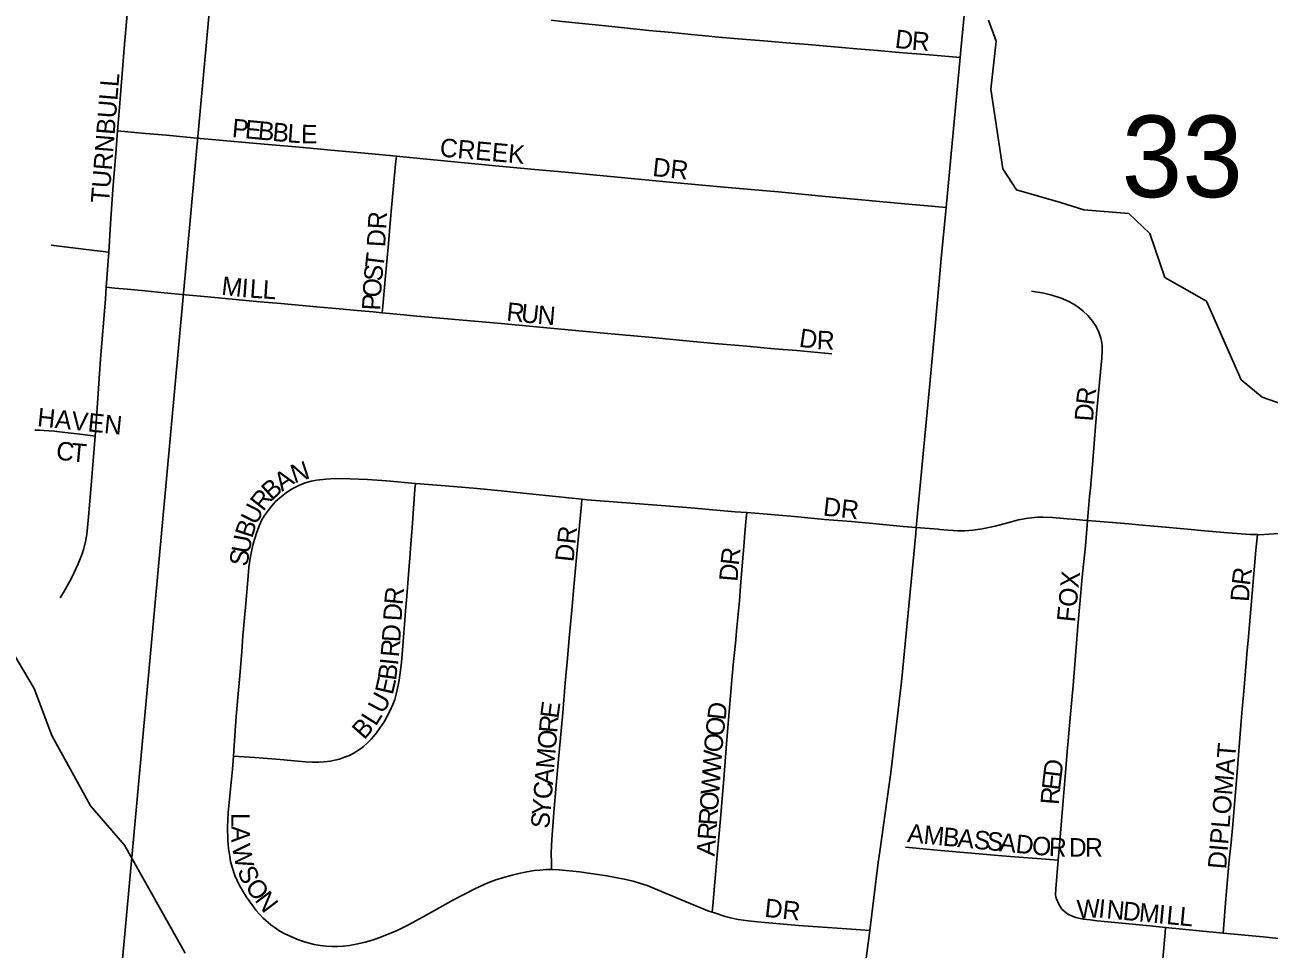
# Model space of a CAD drawing. Extents: x 1410790 to 1770854, y 448063 to 770588.
# Drawn here: x 1528142 to 1531514, y 635499 to 638002 of the extents above; entities that cross this region are included whole.
import ezdxf

# ---------------------------------------------------------------- set-up
doc = ezdxf.new("R2010")
doc.units = 0
for name, color, linetype in [('GM_X_City_Street', 7, 'Continuous'), ('GM_X_City_Street_Text', 7, 'Continuous'), ('GM_X_Minor_River', 7, 'Continuous'), ('GM_X_Section', 7, 'Continuous'), ('GM_X_Section_Text', 7, 'Continuous')]:
    doc.layers.add(name, color=color, linetype=linetype)

msp = doc.modelspace()

# ---------------------------------------------------------------- linework, layer by layer
at = {"layer": 'GM_X_City_Street'}
for points in [[(1528393.4, 637715.4), (1528397.6, 637767.9), (1528412.4, 637949.9), (1528431.1, 638161.5), (1528439.8, 638248), (1528453.8, 638381.2), (1528472.3, 638566.1), (1528485.8, 638700.3), (1528490.8, 638753.3), (1528497.4, 638828.5)], [(1530677.1, 637913.9), (1530679.1, 637934.6), (1530693.2, 638084.8), (1530711.3, 638277.1)], [(1529568.2, 638014.9), (1529597.9, 638011.6), (1529652.5, 638005.9), (1529706.4, 638000.4), (1529767.2, 637994.1), (1529833.5, 637987.6), (1529896.2, 637981.5), (1529947.7, 637976.4), (1529987.2, 637972.5), (1530022.2, 637969.1), (1530075.5, 637964.6), (1530155.9, 637957.9), (1530206.6, 637953.7), (1530265.1, 637948.9), (1530346.6, 637941.8), (1530386.4, 637938.4), (1530453.1, 637932.7), (1530521.5, 637926.8), (1530583.4, 637921.9), (1530625.5, 637918.3), (1530677.1, 637913.9)], [(1530638.8, 637508.1), (1530677.1, 637913.9)], [(1528369.5, 637386.9), (1528374.5, 637463.3), (1528380.6, 637556.3), (1528389.5, 637665.8), (1528393.4, 637715.4)], [(1528393.4, 637715.4), (1528420.9, 637712.9), (1528469.4, 637708.6), (1528525.8, 637703.5), (1528617.1, 637694.8), (1528659.4, 637691.2), (1528770.2, 637681.5), (1528886.8, 637671.3), (1528972.7, 637663.3), (1529072.3, 637654), (1529148.9, 637646.8)], [(1529110.4, 637222.5), (1529112.1, 637241), (1529118.6, 637312.6), (1529127.4, 637410.2), (1529133.4, 637476.5), (1529136.1, 637506.6), (1529141.6, 637566.5), (1529146.9, 637625.2), (1529148.9, 637646.8)], [(1529148.9, 637646.8), (1529212.2, 637640.9), (1529316, 637630.6), (1529399, 637622.7), (1529514.7, 637611.6), (1529596.3, 637604.1), (1529739.6, 637590.5), (1529804.3, 637584.7), (1529908.9, 637575), (1530037.8, 637563.2), (1530151.9, 637552.9), (1530184.4, 637549.8), (1530301.8, 637538.2), (1530399.7, 637529.2), (1530468.2, 637523.4), (1530536.6, 637516.7), (1530609.3, 637510.6), (1530638.8, 637508.1)], [(1530558, 636640.9), (1530594.7, 637029.9), (1530608, 637176.9), (1530620.3, 637307.5), (1530625.8, 637369.6), (1530638.8, 637508.1)], [(1528213.4, 637406.2), (1528249.8, 637401.7), (1528330.9, 637391.7), (1528369.5, 637386.9)], [(1528362.7, 637291.6), (1528369.5, 637386.9)], [(1528332.9, 636888.4), (1528337.5, 636951.2), (1528347.2, 637097.6), (1528353.2, 637172.6), (1528360.6, 637260.8), (1528362.7, 637291.6)], [(1528362.7, 637291.6), (1528386.2, 637289.4), (1528419.2, 637286.3), (1528467.8, 637281.7), (1528519.8, 637276.8), (1528577.2, 637271.5), (1528638.4, 637265.7), (1528693.7, 637260.5), (1528780.2, 637252.7), (1528835.9, 637247.6), (1528932.6, 637238.8), (1528994.4, 637233.1), (1529042.3, 637228.8), (1529085.7, 637224.8), (1529110.4, 637222.5)], [(1531022.4, 636660.2), (1531027.9, 636725.3), (1531030.4, 636747.9), (1531035.5, 636810.8), (1531040.2, 636868.9), (1531046.6, 636948.7), (1531053.1, 637014.8), (1531060.9, 637100.9), (1531061.9, 637119.4), (1531061.4, 637132.4), (1531060.5, 637141.1), (1531057.9, 637154.1), (1531052.6, 637170.3), (1531045.2, 637185.7), (1531035.8, 637199.8), (1531023, 637215.4), (1531010.7, 637227.1), (1530995.7, 637239.2), (1530983.2, 637247.1), (1530969.8, 637254.5), (1530950.8, 637262.3), (1530925.8, 637270.2), (1530903.6, 637275.8), (1530870.3, 637281.3)], [(1529110.4, 637222.5), (1529169, 637217), (1529194.6, 637214.6), (1529432.6, 637193.9), (1529566.3, 637181.3), (1529711.3, 637167.5), (1529843.3, 637155.3), (1529934.8, 637146.8), (1530011.1, 637139.8), (1530098.9, 637131.8), (1530173.2, 637125.3), (1530234.1, 637120.1), (1530291.1, 637114.9), (1530328.8, 637111.5)], [(1528169, 636904.6), (1528181.4, 636904.5), (1528194.5, 636904), (1528207.7, 636903.2), (1528221.9, 636901.7), (1528236.3, 636900.2), (1528268, 636896.4), (1528298.9, 636892.6), (1528332.9, 636888.4)], [(1528238, 636451.1), (1528247.2, 636465), (1528268.1, 636503.6), (1528286.6, 636542.9), (1528297, 636569.5), (1528302.2, 636584.3), (1528306.6, 636602.8), (1528310.3, 636622), (1528314.8, 636670.2), (1528321.5, 636754.5), (1528332.9, 636888.4)], [(1528707.2, 636022.1), (1528709.2, 636050.2), (1528712.1, 636090.4), (1528714.9, 636129.1), (1528719.5, 636181), (1528724.8, 636239.6), (1528730.3, 636305.1), (1528733, 636347.5), (1528741, 636435.4), (1528745.3, 636487.6), (1528749.2, 636532.4), (1528752.8, 636557.7), (1528757.1, 636580.7), (1528761.2, 636596.6), (1528765.4, 636611.8), (1528770.6, 636628.5), (1528777.7, 636647.2), (1528784.7, 636661.7), (1528791.8, 636673.9), (1528807.7, 636695.6), (1528820.9, 636710.7), (1528833.1, 636721.9), (1528851.6, 636736.1), (1528866.7, 636745.8), (1528877.7, 636751.7), (1528886.2, 636755.8), (1528902, 636761.8), (1528918.4, 636766.8), (1528932.9, 636769.6), (1528957.7, 636772.2), (1528984.3, 636773.6), (1529022.5, 636773.4), (1529070.4, 636771), (1529122, 636767.9), (1529200.4, 636760.7)], [(1528707.2, 636022.1), (1528765.1, 636018.3), (1528834, 636012.4), (1528901.6, 636006.5), (1528922.1, 636005.4), (1528938, 636005.7), (1528953.5, 636006.5), (1528970.1, 636008.5), (1528981.8, 636010.6), (1528995, 636013.9), (1529008.8, 636018.7), (1529021.9, 636024.1), (1529032, 636029.4), (1529041.9, 636035.5), (1529051.4, 636041.9), (1529059.8, 636048.4), (1529070.1, 636057.2), (1529080.7, 636068.1), (1529087.2, 636075.5), (1529094.8, 636084.9), (1529105.2, 636099.3), (1529116.1, 636115.2), (1529124.4, 636129.8), (1529131.2, 636143.9), (1529139.4, 636162.2), (1529144.4, 636175.7), (1529148.6, 636189.7), (1529153.3, 636209.9), (1529156.8, 636227.5), (1529162.7, 636275.6), (1529165.9, 636309.1), (1529169.4, 636355.6), (1529171.6, 636389.8), (1529173.8, 636415.9), (1529177.3, 636454.9), (1529181.6, 636513.7), (1529185.2, 636559.2), (1529188.1, 636596.4), (1529191.6, 636640.4), (1529195.7, 636692.7), (1529199.3, 636744.7), (1529200.4, 636760.7)], [(1529200.4, 636760.7), (1529213.4, 636759.6), (1529314.3, 636751.3), (1529368.2, 636746.9), (1529433, 636740.7), (1529509.6, 636732.5), (1529581.2, 636724.9), (1529651.7, 636717.8)], [(1529569.6, 635715.1), (1529569.3, 635730), (1529568.8, 635761.4), (1529570.1, 635796.5), (1529576.1, 635868.9), (1529582.4, 635943), (1529588.4, 636013.9), (1529592.7, 636061.4), (1529599.7, 636139.6), (1529606.8, 636220.2), (1529612.8, 636286.8), (1529617.7, 636341.1), (1529624.6, 636417.7), (1529631.2, 636490.8), (1529639.2, 636579.6), (1529650.4, 636703.5), (1529651.7, 636717.8)], [(1529651.7, 636717.8), (1529665.9, 636716.3), (1529878.3, 636700.1), (1529947, 636694.4), (1530007, 636689.2), (1530067.6, 636683.9), (1530098.5, 636681.5)], [(1530004.9, 635599.1), (1530006.6, 635617.5), (1530012.3, 635680.9), (1530019.7, 635763.8), (1530026.4, 635842.3), (1530036.2, 635960.4), (1530044.1, 636055), (1530056.2, 636208), (1530062.1, 636269.4), (1530067.8, 636328.2), (1530071.9, 636370.2), (1530078.8, 636442.7), (1530082, 636482.6), (1530087.2, 636548.1), (1530090.7, 636589.9), (1530093.8, 636625.6), (1530097.3, 636666.5), (1530098.5, 636681.5)], [(1530098.5, 636681.5), (1530142.7, 636678.1), (1530227.6, 636670.8), (1530309.5, 636663.2), (1530382.2, 636657.2), (1530439.9, 636652), (1530522.1, 636644.3), (1530558, 636640.9)], [(1530558, 636640.9), (1530617, 636636.6), (1530622.1, 636636.1), (1530644.1, 636633.8), (1530658.3, 636632.8), (1530670.8, 636632.3), (1530690, 636632.3), (1530710.9, 636634.3), (1530736.4, 636637.9), (1530771.4, 636645), (1530812.5, 636656), (1530834.9, 636661.6), (1530861, 636666.3), (1530887.5, 636668.9), (1530900.7, 636669.3), (1530927.2, 636668.2), (1530966.6, 636665), (1530991.6, 636662.6), (1531018.7, 636660.5), (1531022.4, 636660.2)], [(1530942.5, 635740.4), (1530947.8, 635802.9), (1530955.9, 635902.2), (1530962.4, 635977.6), (1530967, 636034.5), (1530969.3, 636063.4), (1530975, 636125.3), (1530982.8, 636213.4), (1530996, 636373.5), (1531004.3, 636464.8), (1531007.1, 636497.3), (1531009.8, 636523.4), (1531016.2, 636591.8), (1531021.3, 636647.2), (1531022.4, 636660.2)], [(1531022.4, 636660.2), (1531090.2, 636654.4), (1531133.5, 636651.1), (1531161.2, 636648.6), (1531201.4, 636644.9), (1531223.3, 636642.9), (1531302.8, 636635.7), (1531329.2, 636633.3), (1531402.4, 636627), (1531438.4, 636624.2), (1531463.9, 636622.2), (1531482.4, 636621.9)], [(1531482.4, 636621.9), (1531488.9, 636621.7), (1531513.9, 636622.7), (1531543.3, 636624.6), (1531575.5, 636627.5), (1531613.3, 636630.7), (1531638.9, 636632.9), (1531685.2, 636636.7), (1531744.3, 636642.4), (1531816.4, 636649.3), (1531864.8, 636653.7), (1531913.6, 636657.8), (1531946.2, 636660.6)], [(1530494.5, 636024), (1530518.1, 636223.4), (1530556.5, 636624.9), (1530558, 636640.9)], [(1531389.7, 635542.5), (1531391.5, 635566.1), (1531396.1, 635624.6), (1531400.8, 635676.7), (1531405.7, 635740.5), (1531411.2, 635787.6), (1531414.8, 635826.7), (1531426.5, 635966.7), (1531438.9, 636116.8), (1531441.6, 636149.4), (1531446.4, 636208.1), (1531455.2, 636309.2), (1531457.3, 636335.3), (1531468.2, 636462.6), (1531478.7, 636579.9), (1531482.4, 636621.9)], [(1528707.2, 636022.1), (1528704.8, 635986.6), (1528693.2, 635869.1), (1528691.3, 635829.5), (1528692.4, 635793.1), (1528694.2, 635771.8), (1528697.2, 635750.3), (1528699.7, 635736.8), (1528703.7, 635721), (1528711.4, 635698.8), (1528717.4, 635685.1), (1528724.2, 635671.6), (1528743.1, 635640.4), (1528757, 635620.3), (1528768.1, 635605.2), (1528788.1, 635582.7), (1528808.3, 635565), (1528833.3, 635548.1), (1528846.3, 635540.8), (1528863.1, 635533.1), (1528883.9, 635524.5), (1528900.3, 635518.8), (1528926, 635511.9), (1528942.8, 635508.7), (1528959, 635507), (1528974.9, 635506.4), (1528989, 635506.2), (1529004.9, 635507.1), (1529022.1, 635509.2), (1529044.2, 635513.3), (1529064.3, 635518), (1529087.1, 635524.8), (1529108.4, 635532.3), (1529151.1, 635550.1), (1529183.6, 635566.4), (1529229.7, 635591.6), (1529304.1, 635632.8), (1529361.6, 635662.9), (1529397, 635678.6), (1529418.8, 635686.7), (1529436.8, 635692.6), (1529463, 635699.8), (1529481, 635704.1), (1529498.3, 635707.7), (1529522.4, 635711.8), (1529538.2, 635713.5), (1529554.6, 635714.7), (1529569.6, 635715.1)], [(1530431.9, 635549.8), (1530443.2, 635638.3), (1530454.8, 635733.6), (1530459.1, 635763.9), (1530489, 635977.3), (1530494.5, 636024)], [(1530528.9, 635775), (1530614.5, 635767.1), (1530789.9, 635752.3), (1530931.9, 635741.2), (1530942.5, 635740.4)], [(1530952.2, 635607.5), (1530945.8, 635617.7), (1530941.3, 635627.1), (1530937.9, 635635.7), (1530936.3, 635640.8), (1530935.6, 635646.4), (1530936, 635662.6), (1530942.5, 635740.4)], [(1529569.6, 635715.1), (1529590.2, 635714.4), (1529645.3, 635709), (1529719.6, 635698), (1529770.7, 635687.9), (1529790.4, 635683.4), (1529808.3, 635678.1), (1529828.3, 635671.6), (1529857.1, 635660.2), (1529923.2, 635631.7), (1529993, 635603), (1530004.9, 635599.1)], [(1530952.2, 635607.5), (1530964.3, 635597.4), (1530970.3, 635592.7), (1530978.6, 635589), (1530990.6, 635585), (1531010.5, 635580.7), (1531029, 635578.4), (1531047.9, 635576.2), (1531181.6, 635563.2), (1531233.4, 635558)], [(1530004.9, 635599.1), (1530011, 635597.1), (1530039.9, 635587.8), (1530058, 635583.3), (1530075.5, 635579.8), (1530102.2, 635575.5), (1530127.8, 635572.8), (1530239.1, 635563.3), (1530369.8, 635554.1), (1530431.9, 635549.8)], [(1530389.2, 635137), (1530390.8, 635183.7), (1530398, 635272.8), (1530416.1, 635426.5), (1530431.9, 635549.8)], [(1531185, 635057.2), (1531187.3, 635079.5), (1531205.2, 635259.2), (1531220.6, 635412.8), (1531232.1, 635543.7), (1531233.4, 635558)], [(1531233.4, 635558), (1531380.6, 635543.3), (1531389.7, 635542.5)], [(1531389.7, 635542.5), (1531498.2, 635532.8), (1531573.3, 635524.6), (1531609.2, 635518.8), (1531638.3, 635511.7), (1531669.8, 635501), (1531697.2, 635489.4), (1531723.9, 635477.5), (1531751.4, 635468.3), (1531779.6, 635461.4), (1531811.6, 635456.3), (1531846.1, 635452.7)]]:
    msp.add_lwpolyline(points, dxfattribs=at)
at = {"layer": 'GM_X_Minor_River'}
for points in [[(1528576.5, 635488.3), (1528411.8, 635780.8), (1528319.7, 635887.1), (1528215.2, 636077.9), (1528167.5, 636205.3), (1528062.7, 636380.1), (1527911, 636722.3), (1527903, 636830.8), (1527937.2, 636942.3), (1527939.9, 637086.7), (1527902.8, 637450.4), (1527991.7, 637699.1), (1527919, 637879.2), (1527866.9, 637982.6), (1527856.3, 638161.3)], [(1530753.8, 638014.8), (1530774.7, 637958.2), (1530760.2, 637828.2), (1530792.2, 637612.9), (1530829.2, 637556), (1530948.7, 637521.3), (1531012.4, 637501.8), (1531134.4, 637491.1), (1531191.4, 637437.7), (1531231.2, 637318.5), (1531344.2, 637253.9), (1531438.3, 637041.2), (1531495.5, 636993.9), (1531678.5, 636929.7)]]:
    msp.add_lwpolyline(points, dxfattribs=at)
at = {"layer": 'GM_X_Section'}
for points in [[(1528881.3, 640647.9), (1528392.9, 635323.7), (1523175.4, 635852.3), (1523663.4, 641153)], [(1534160.3, 640098.2), (1533718.1, 634783.3), (1528392.9, 635323.7), (1528881.3, 640647.9)]]:
    msp.add_lwpolyline(points, close=True, dxfattribs=at)

# ---------------------------------------------------------------- texts
at = {"layer": 'GM_X_City_Street_Text'}
for s, rotation, p in [('D', 353.1203, (1530498.4, 637940.7)), ('R', 355.6207, (1530544.4, 637935.2)), ('TURNBULL', 85.4243, (1528370.5, 637518.4)), ('P', 354.583, (1528702, 637698.9)), ('E', 354.6039, (1528737, 637695.6)), ('B', 354.5769, (1528772.1, 637692.3)), ('B', 354.6007, (1528811.5, 637688.5)), ('L', 355.6693, (1528852, 637684.7)), ('E', 359.1677, (1528890.3, 637681.9)), ('CREEK', 354.9006, (1529265.1, 637646.1)), ('DR', 353.9832, (1529841.6, 637593.3)), ('DR', 86.8222, (1529118.5, 637399.7)), ('T', 82.9461, (1529113.4, 637341.2)), ('S', 84.0746, (1529109.8, 637306.4)), ('M', 353.3742, (1528673.2, 637271.8)), ('I', 355.9304, (1528728, 637265.5)), ('L', 356.1821, (1528750.2, 637263.9)), ('L', 356.2072, (1528785.3, 637261.6)), ('O', 86.5232, (1529107.2, 637263.1)), ('P', 86.9111, (1529105.3, 637228)), ('R', 353.9656, (1529445.7, 637201.7)), ('U', 353.9567, (1529485.1, 637197.5)), ('N', 355.2861, (1529530.1, 637192.8)), ('D', 351.7308, (1530238.5, 637131.2)), ('R', 357.4807, (1530287.4, 637124.4)), ('R', 82.3508, (1531040, 636970.5)), ('HAVEN', 354.1748, (1528174.1, 636915.7)), ('D', 85.7882, (1531036.8, 636927.4)), ('C', 352.5241, (1528224.6, 636826)), ('T', 354.7893, (1528266, 636820.6)), ('N', 18.1343, (1528872.2, 636760.4)), ('A', 33.8174, (1528838.9, 636737.5)), ('B', 41.813, (1528810.9, 636712.3)), ('R', 51.8428, (1528788, 636682.8)), ('DR', 353.6631, (1530303.7, 636673.7)), ('U', 63.3372, (1528769.6, 636645.7)), ('B', 71.6841, (1528757.9, 636609.9)), ('U', 79.9281, (1528750.7, 636568.4)), ('DR', 83.9877, (1529628.9, 636546.5)), ('R', 83.4654, (1530076.9, 636536.8)), ('S', 79.9224, (1528744.5, 636533.8)), ('D', 85.24, (1530073.3, 636493.4)), ('FOX', 84.2878, (1530988.5, 636383.5)), ('R', 82.8539, (1531462.2, 636482.2)), ('D', 86.0514, (1531459.2, 636439)), ('R', 84.345, (1529165.5, 636430.1)), ('D', 86.4526, (1529162.9, 636386.7)), ('D', 86.447, (1529159.3, 636329.6)), ('R', 84.8899, (1529155.7, 636288.7)), ('I', 84.0125, (1529153.3, 636266.1)), ('B', 82.1967, (1529147.7, 636225.1)), ('E', 77.0596, (1529139, 636186.1)), ('U', 62.0186, (1529113.4, 636134.1)), ('E', 82.6581, (1529588.1, 636122.3)), ('D', 83.1542, (1530040.8, 636117.6)), ('B', 48.7889, (1529061.7, 636064.3)), ('L', 58.0003, (1529092.9, 636101)), ('R', 85.1628, (1529584.8, 636083.4)), ('O', 83.2627, (1530035.7, 636073.9)), ('O', 85.1561, (1529581.1, 636039.6)), ('O', 84.8679, (1530031.8, 636030.4)), ('DIPLOMAT', 85.3007, (1531397.7, 635714.6)), ('M', 85.1486, (1529576.6, 635986.9)), ('W', 85.9028, (1530027.7, 635973.6)), ('D', 83.1542, (1530951.6, 635962.8)), ('A', 85.1561, (1529572.9, 635943.1)), ('W', 85.9028, (1530023.6, 635916.6)), ('C', 85.1496, (1529569.6, 635903.6)), ('E', 83.3867, (1530947.5, 635927.9)), ('O', 85.9057, (1530020.5, 635872.7)), ('R', 85.4663, (1530944.4, 635888.9)), ('Y', 85.1561, (1529565.9, 635859.8)), ('R', 85.9023, (1530017.7, 635833.2)), ('L', 270.2049, (1528701.7, 635867.9)), ('S', 85.1592, (1529562.9, 635824.7)), ('R', 85.9023, (1530014.8, 635793.7)), ('A', 270.2012, (1528701.8, 635832.7)), ('A', 354.3742, (1530532.4, 635789.3)), ('M', 354.3628, (1530576.2, 635785)), ('B', 354.3736, (1530628.7, 635779.8)), ('A', 354.3525, (1530668.1, 635775.9)), ('S', 354.3818, (1530712, 635771.6)), ('S', 354.3628, (1530747, 635768.2)), ('A', 354.3661, (1530782, 635764.7)), ('D', 354.3661, (1530825.8, 635760.4)), ('W', 281.2727, (1528703, 635778.2)), ('A', 85.8988, (1530011.7, 635749.8)), ('O', 354.3514, (1530869.6, 635756.1)), ('R', 357.5878, (1530916.4, 635751.5)), ('D', 359.9533, (1530971.5, 635749.8)), ('R', 359.9941, (1531015.5, 635749.8)), ('S', 291.8901, (1528717.1, 635712.5)), ('O', 306.401, (1528736.9, 635667.7)), ('N', 307.1553, (1528763.5, 635631.8)), ('DR', 353.9946, (1530145.3, 635586.9)), ('W', 3.2465, (1530994.8, 635581.9)), ('I', 354.0001, (1531049.8, 635585.2)), ('N', 354.5232, (1531072.2, 635582.9)), ('D', 354.5627, (1531116, 635578.7)), ('M', 354.5459, (1531159.8, 635574.5)), ('I', 354.565, (1531212.4, 635569.5)), ('L', 354.5545, (1531234.3, 635567.4)), ('L', 354.5545, (1531269.3, 635564.1))]:
    msp.add_text(s, height=50, rotation=rotation, dxfattribs=at).set_placement(p)
at = {"layer": 'GM_X_Section_Text'}
msp.add_text('33', height=221, rotation=0, dxfattribs=at).set_placement((1531114.5, 637535.8))

doc.saveas('drawing.dxf')
